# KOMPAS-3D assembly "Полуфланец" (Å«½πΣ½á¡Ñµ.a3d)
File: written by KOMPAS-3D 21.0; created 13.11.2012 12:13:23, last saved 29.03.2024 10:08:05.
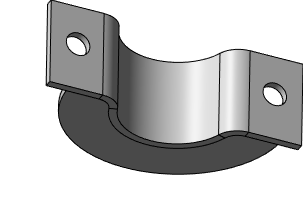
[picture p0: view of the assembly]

Document properties: Автор: Владимир Бескаравайный; Полное имя файла: D:\Save\YandexDisk\Документы_sh\Exch\Для форума АСКОН\18 SAT и поверхности\Кронштейн тяговый\Полуфланец.a3d

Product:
- Part/product: Полуфланец
    Материал: Сталь 3сп ГОСТ 380-2005 (density 7850 kg/m3)
    Масса: 0.03662
  - Body: Поверхность 7
      Материал: Сталь 3сп ГОСТ 380-2005 (density 0 kg/m3)
  - Body: Поверхность 6
      Материал: Сталь 3сп ГОСТ 380-2005 (density 0 kg/m3)
  - Body: Полушайба  | pos. 1
      Масса: 0.011272
      Раздел спецификации: Детали
      Примечание: Лист $dБ-ПН-0-2 ГОСТ 19904-90;Ст3сп5-св ГОСТ 14637-89$
  - Body: Полускоба  | pos. 2
      Масса: 0.025347
      Раздел спецификации: Детали
      Примечание: Лист $dБ-ПН-0-2 ГОСТ 19904-90;Ст3сп5-св ГОСТ 14637-89$

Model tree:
1. Копирование:1
2. Проекция полуфланца спереди
3. Низ полушайбы
4. Проекция полуфланца сверху
5. Низ хомута
6. Эскиз:20
7. Эскиз:21
8. Эскиз:22
9. Скругление:1
10. Отверстие (зеркало)
11. Экземпляр ( 1 )
12. Экземпляр ( 2 )  (with: Отверстие)  (labels: Сталь 3сп ГОСТ 380-2005)

Expressions: s*2
Referenced files in D:\Проекты\НБТ\18 Подсборки\K3D\Змеевик продуктовый\Кронштейн тяговый\: Корпус кроншт тягового.a3d
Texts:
  Точка начала. Х
  Точка начала. Y
  Точка начала. Z
  Копия грани : Полушайба
  Копия грани : Полушайба сверху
